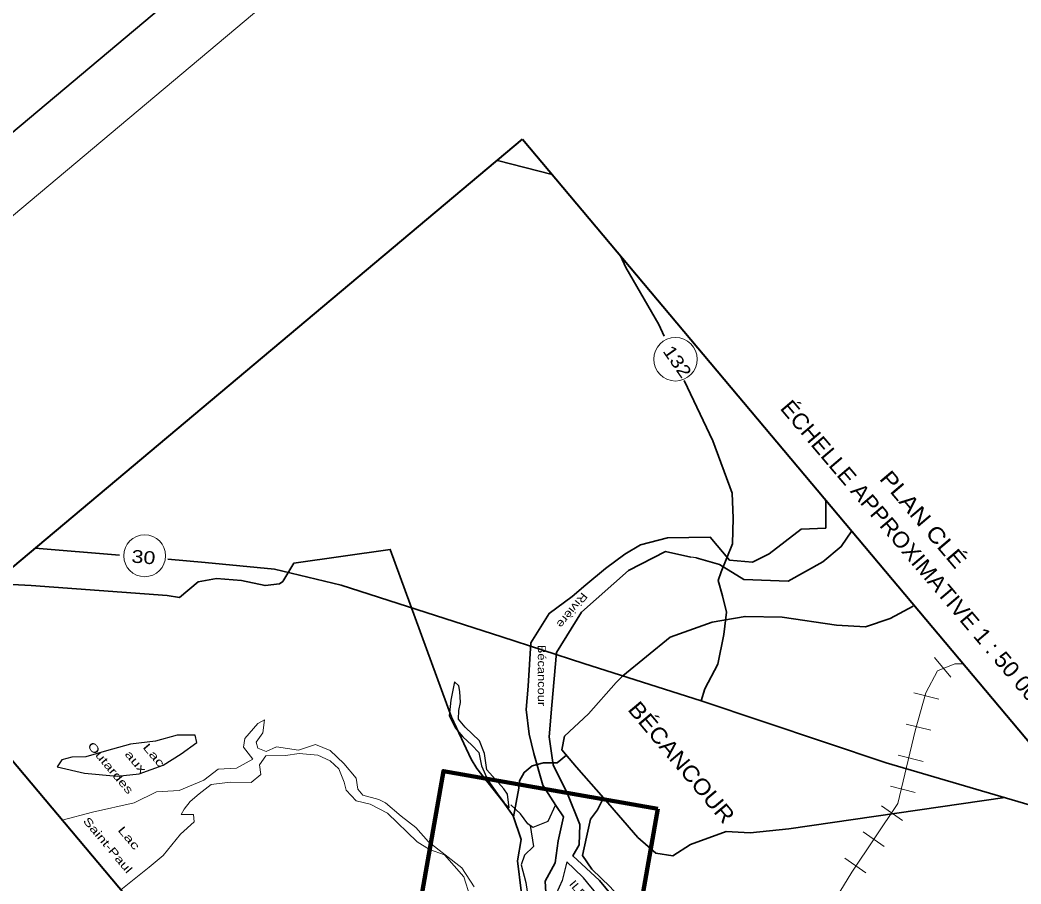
# Model space of a CAD drawing. Extents: x 386081 to 389416, y 5130568 to 5134082.
# Drawn here: x 388435.3 to 388747.8, y 5131306.8 to 5131576.7 of the extents above; entities that cross this region are included whole.
import ezdxf

# ---------------------------------------------------------------- set-up
doc = ezdxf.new("R2010")
doc.units = 0
doc.header["$LTSCALE"] = 1.2
doc.layers.add('60', color=7, linetype='Continuous', lineweight=13)
doc.layers.add('63', color=7, linetype='Continuous', lineweight=13)

msp = doc.modelspace()

# ---------------------------------------------------------------- linework, layer by layer
at = {"layer": '60', "lineweight": 35}
msp.add_lwpolyline([(386109.63, 5132985.69), (387380.72, 5134053.36), (389052.99, 5132062.51), (387781.9, 5130994.83)], close=True, dxfattribs=at)
at = {"layer": '60'}
msp.add_lwpolyline([(389387.44, 5131664.33), (388116.36, 5130596.66), (387794.77, 5130979.51), (389065.85, 5132047.19)], close=True, dxfattribs=at)
at = {"layer": '63', "lineweight": 35}
for p, q in [((388584.23, 5131532.85), (388584.34, 5131532.82)), ((388584.34, 5131532.82), (388601.42, 5131528.48)), ((388466.37, 5131409.56), (388440.07, 5131411.75))]:
    msp.add_line(p, q, dxfattribs=at)
at = {"layer": '63', "lineweight": 25}
msp.add_line((388646.47, 5131408.7), (388644.71, 5131408.94), dxfattribs=at)
at = {"layer": '63'}
for p, q in [((388725.91, 5131371.38), (388720.85, 5131377.57)), ((388722.17, 5131364.52), (388714.41, 5131366.48)), ((388719.72, 5131354.82), (388711.96, 5131356.78)), ((388717.27, 5131345.13), (388709.51, 5131347.09)), ((388714.82, 5131335.43), (388707.06, 5131337.39)), ((388710.82, 5131326.69), (388704.26, 5131331.27)), ((388705.1, 5131318.49), (388698.54, 5131323.07)), ((388699.37, 5131310.29), (388692.81, 5131314.87))]:
    msp.add_line(p, q, dxfattribs=at)
at = {"layer": '63', "lineweight": 40}
msp.add_lwpolyline([(388592.16, 5131539.51), (388812.37, 5131277.36), (388623.34, 5131118.57), (388403.13, 5131380.72)], close=True, dxfattribs=at)
at = {"layer": '63', "lineweight": 35}
for points in [[(388622.79, 5131503.04), (388624.49, 5131499.34), (388634.77, 5131481.56), (388636.43, 5131477.9)], [(388642.69, 5131464.12), (388651.66, 5131445.26), (388657.62, 5131428.91), (388657.99, 5131421.06), (388657.72, 5131413.06), (388654.21, 5131404.29), (388653.34, 5131401.62), (388654.61, 5131396.86), (388655.85, 5131391.68), (388655.04, 5131384.79), (388653.17, 5131375.45), (388649.12, 5131367.77), (388647.95, 5131364.01)], [(388604.99, 5131327.82), (388602.64, 5131331.34), (388598.55, 5131337.67), (388595.75, 5131347.54), (388594.3, 5131353.65), (388593.31, 5131361.37), (388593.94, 5131368.62), (388594.79, 5131382.15), (388600.57, 5131391.28), (388607.68, 5131396.64), (388611.98, 5131400.25), (388618.07, 5131405.37), (388624.1, 5131409.83), (388629, 5131412.72), (388637.5, 5131414.97), (388650.8, 5131415.15), (388656.81, 5131407.99), (388664.06, 5131407.36), (388669.26, 5131409.9), (388679.24, 5131417.66), (388686.9, 5131418), (388686.93, 5131425.96), (388686.84, 5131426.8)], [(388694.99, 5131417.1), (388691.71, 5131412.26), (388685.98, 5131407.44), (388675.16, 5131401.41), (388661.26, 5131401.95), (388653.7, 5131406.59), (388646.47, 5131408.7)], [(388426.89, 5131400.68), (388438.83, 5131400.04), (388481.2, 5131396.97), (388485.05, 5131396.34), (388490.88, 5131401.24), (388496.68, 5131402.24), (388504.42, 5131401.57), (388511.8, 5131400.03), (388516.35, 5131400.53), (388517.32, 5131401.35), (388520.82, 5131407.05), (388550.92, 5131411.35), (388570.07, 5131358.94), (388576.13, 5131345.81), (388577.99, 5131342.94), (388586.17, 5131332.46), (388589.31, 5131328.15)], [(388772.15, 5131325.25), (388756.45, 5131329.76), (388705.8, 5131344.71), (388647.95, 5131364.01), (388611.38, 5131375.7), (388585.71, 5131384.05), (388535.6, 5131400.21), (388514.71, 5131405.19), (388493.14, 5131407.27), (388481.42, 5131408.28)], [(388644.71, 5131408.94), (388636.8, 5131410.71), (388625.32, 5131404.73), (388610.57, 5131391.73), (388602.83, 5131379.12), (388601.39, 5131362.65), (388600.53, 5131352.76), (388601.76, 5131344.03), (388606.28, 5131335), (388610.09, 5131325.38), (388609.87, 5131319.09), (388607.91, 5131315.6), (388616.2, 5131307.91), (388622.22, 5131300.75)], [(388742.78, 5131333.8), (388675.41, 5131324.07), (388663.32, 5131322.8), (388655.82, 5131323.25), (388644.64, 5131319.2), (388639.11, 5131315.62), (388633.78, 5131316.47), (388628.21, 5131321.39), (388617.51, 5131333.72), (388609.06, 5131343.34), (388604.51, 5131348.76), (388605.26, 5131352.95), (388612.84, 5131360.02), (388621.42, 5131369.72), (388623.52, 5131371.82), (388638.31, 5131383.91), (388651.47, 5131388.56), (388661.68, 5131390.38), (388673.26, 5131390.15), (388690.24, 5131387.72), (388699.28, 5131387.13), (388707.04, 5131389.74), (388714.14, 5131393.57)], [(388605.91, 5131347.1), (388602.99, 5131344.64), (388598.73, 5131344.63), (388595.18, 5131343.77), (388592.68, 5131341.67), (388591.29, 5131339.09), (388591.09, 5131336.79), (388589.43, 5131327.8)], [(388640.59, 5131133.06), (388643.3, 5131144.23), (388642.91, 5131155.28), (388641.85, 5131169.67), (388641.34, 5131185.95), (388639.53, 5131202.91), (388640.21, 5131217.35), (388640.73, 5131227.74), (388637.38, 5131238.08), (388632.68, 5131246.22), (388624.56, 5131255.04), (388622.15, 5131258.34), (388624.05, 5131271.32), (388626.86, 5131285.76), (388623.67, 5131291.25), (388624.64, 5131300.25), (388619.53, 5131305.91), (388613.83, 5131311.43), (388610.92, 5131315.74), (388612.19, 5131321.43), (388613.46, 5131327.12), (388615.65, 5131330.02), (388617.51, 5131333.72)], [(388589.31, 5131328.15), (388591.83, 5131320.68), (388590.67, 5131314.02), (388591.78, 5131304.65)], [(388599.64, 5131300.72), (388599.25, 5131307.72), (388602.41, 5131313.43), (388603.34, 5131320.32), (388604.99, 5131327.82)]]:
    msp.add_lwpolyline(points, dxfattribs=at)
at = {"layer": '63', "lineweight": 25}
for points in [[(388604.99, 5131327.82), (388602.64, 5131331.34), (388598.55, 5131337.67), (388595.75, 5131347.54), (388594.3, 5131353.65), (388593.31, 5131361.37), (388593.94, 5131368.62), (388594.79, 5131382.15), (388600.57, 5131391.28), (388607.68, 5131396.64), (388611.98, 5131400.25), (388618.07, 5131405.37), (388624.1, 5131409.83), (388629, 5131412.72), (388637.5, 5131414.97), (388650.8, 5131415.15), (388656.81, 5131407.99), (388664.06, 5131407.36), (388669.26, 5131409.9), (388679.24, 5131417.66), (388686.9, 5131418), (388686.93, 5131425.96), (388686.84, 5131426.8)], [(388694.99, 5131417.1), (388691.71, 5131412.26), (388685.98, 5131407.44), (388675.16, 5131401.41), (388661.26, 5131401.95), (388653.7, 5131406.59), (388646.47, 5131408.7)], [(388644.71, 5131408.94), (388636.8, 5131410.71), (388625.32, 5131404.73), (388610.57, 5131391.73), (388602.83, 5131379.12), (388601.39, 5131362.65), (388600.53, 5131352.76), (388601.76, 5131344.03), (388606.28, 5131335), (388610.09, 5131325.38), (388609.87, 5131319.09), (388607.91, 5131315.6), (388616.2, 5131307.91), (388622.22, 5131300.75)], [(388602.5, 5131331.55), (388600.06, 5131326.34), (388595.38, 5131324.48), (388593.86, 5131325.58), (388591.55, 5131328.69), (388588.56, 5131331.53)], [(388599.64, 5131300.72), (388599.25, 5131307.72), (388602.41, 5131313.43), (388603.34, 5131320.32), (388604.99, 5131327.82)], [(388594.57, 5131325.07), (388595.66, 5131318.49), (388592.84, 5131315.83), (388591.78, 5131312.85), (388593.22, 5131307.24), (388594.03, 5131301.68), (388594.91, 5131298.86), (388597.14, 5131296.57), (388596.92, 5131290.45), (388595.51, 5131287.18), (388598.26, 5131283.56), (388600.89, 5131280.42), (388602.82, 5131278.48), (388604.14, 5131275.14), (388603.98, 5131271.44), (388603.7, 5131268.23), (388604.19, 5131262.7), (388604.64, 5131258.63)]]:
    msp.add_lwpolyline(points, dxfattribs=at)
at = {"layer": '63'}
for points in [[(388524.99, 5131235.66), (388553.61, 5131241.09), (388590.57, 5131247.86), (388613.67, 5131252.16), (388634.24, 5131255.95), (388640.61, 5131258.33), (388676.35, 5131284.85), (388689.02, 5131300.62), (388695.01, 5131310.51), (388709.35, 5131331.99), (388714.85, 5131354.68), (388718.09, 5131366.57), (388721.77, 5131373.44), (388727.23, 5131375.6), (388729.87, 5131375.58)], [(388577.13, 5131305.89), (388573.29, 5131311.87), (388562.87, 5131320.04), (388558.89, 5131324.42), (388554.36, 5131328.04), (388549.4, 5131332.18), (388547.39, 5131333.17), (388542.34, 5131334.57), (388540.73, 5131336.49), (388540.23, 5131339.92), (388536.42, 5131344.45), (388532.1, 5131348.53), (388527.58, 5131350.38), (388522.26, 5131348.58), (388515.41, 5131349.66), (388512.21, 5131348.16), (388509.56, 5131349.2), (388509.08, 5131351.17), (388511.11, 5131354.07), (388511.62, 5131358.06), (388509.59, 5131356.94), (388505.47, 5131352.29), (388505.07, 5131349.58), (388507.97, 5131345.78), (388502.88, 5131342.99), (388497.21, 5131342.68), (388492.7, 5131339.2), (388485, 5131335.99), (388477.87, 5131335.64), (388470.95, 5131332.2), (388457.94, 5131329.3), (388448.5, 5131326.71), (388466.78, 5131304.95), (388475.65, 5131312.1), (388480, 5131315.76), (388485.43, 5131322.39), (388489.63, 5131326.23), (388489.51, 5131328.5), (388487.73, 5131328.49), (388485.64, 5131328.51), (388486.59, 5131330.2), (388488.42, 5131332.63), (388491.2, 5131334.97), (388495.01, 5131337.87), (388500.89, 5131338.65), (388507.5, 5131338.56), (388510.46, 5131341.05), (388510.07, 5131343.99), (388512.1, 5131346.88), (388518.24, 5131346.99), (388522.49, 5131347.59), (388528.26, 5131347.09), (388532.14, 5131345.3), (388534.83, 5131342.81), (388536.56, 5131338.62), (388537.15, 5131336.15), (388540.25, 5131332.82), (388544.68, 5131331.79), (388550.08, 5131328.9), (388559.31, 5131320.03), (388563.14, 5131317.6), (388567.83, 5131315.9), (388573.86, 5131309.08), (388575.89, 5131302.77)]]:
    msp.add_lwpolyline(points, dxfattribs=at)
at = {"layer": '63', "lineweight": 25}
for points in [[(388571, 5131370), (388569.86, 5131364.29), (388569.27, 5131359.34), (388571.2, 5131355.62), (388573.54, 5131352.83), (388576.38, 5131350.17), (388578.6, 5131347.88), (388579.37, 5131343.77), (388581.39, 5131339.24), (388584.41, 5131334.94), (388586.43, 5131332.19), (388588.06, 5131330.59), (388587.49, 5131334.88), (388586.33, 5131336.55), (388581.03, 5131342.5), (388580.35, 5131347.56), (388578.76, 5131351.57), (388574.29, 5131355.84), (388572.24, 5131358.27), (388572.32, 5131361.01), (388572.86, 5131363.55), (388572.67, 5131366.95), (388572.35, 5131368.76)], [(388446.88, 5131343.45), (388455.42, 5131341.42), (388465.68, 5131340.53), (388472.52, 5131341.23), (388480.02, 5131343.97), (388485.66, 5131347.52), (388490.48, 5131350.98), (388490.03, 5131353.27), (388484.39, 5131353.28), (388477.61, 5131351.45), (388469.78, 5131350.51), (388462.33, 5131348.41), (388455.87, 5131346.55), (388451.5, 5131346.44), (388448.36, 5131345.59)], [(388606, 5131313.69), (388604.62, 5131307.88), (388602.71, 5131303.77), (388604.04, 5131299), (388606.88, 5131293.7), (388610.98, 5131289.46), (388614.21, 5131288.59), (388616.48, 5131290.15), (388617.69, 5131294.02), (388618.59, 5131297.64), (388616.49, 5131302.48), (388613.58, 5131305.94), (388611.21, 5131308.77), (388608.34, 5131311.54)]]:
    msp.add_lwpolyline(points, close=True, dxfattribs=at)
at = {"layer": '63', "lineweight": 158}
msp.add_lwpolyline([(388634.46, 5131330.34), (388616.46, 5131227.91), (388549.49, 5131239.68), (388567.5, 5131342.11)], close=True, dxfattribs=at)
at = {"layer": '63'}
for centre, radius in [((388639.957, 5131470.73), 6.795), ((388474.221, 5131409.336), 6.543)]:
    msp.add_circle(centre, radius, dxfattribs=at)

# ---------------------------------------------------------------- texts
for s, height, rotation, width, p in [('132', 4, 305.029, 1.2, (388635.83, 5131473.24)), ('ÉCHELLE APPROXIMATIVE 1 : 50 000', 5, 310.295, 1.05, (388672.39, 5131455.31)), ('PLAN CLÉ', 5, 310.295, 1.15, (388703.38, 5131433.28)), ('30', 4, 355.029, 1.25, (388469.98, 5131407.26)), ('Rivière ', 2.5, 231.085, 1.25, (388610.79, 5131398.13)), ('Bécancour', 2.5, 270.029, 1.2, (388596.98, 5131381.54)), ('BÉCANCOUR', 5, 310.029, 1.1, (388624.83, 5131361.22)), ('Outardes', 2.5, 310.029, 1.45, (388456.19, 5131349.91)), ('Lac', 2.5, 310.029, 1.55, (388473.46, 5131349.44)), ('aux', 2.5, 310.029, 1.5, (388467.84, 5131347.27)), ('Saint-Paul', 2.5, 310.029, 1.4, (388454.81, 5131326.43)), ('Lac', 2.5, 310.029, 1.55, (388465.66, 5131323.59)), ('ILE DES', 2.5, 310.029, 1.25, (388606.59, 5131306.72))]:
    msp.add_text(s, height=height, rotation=rotation, dxfattribs=dict(at, width=width)).set_placement(p)

doc.saveas('drawing.dxf')
